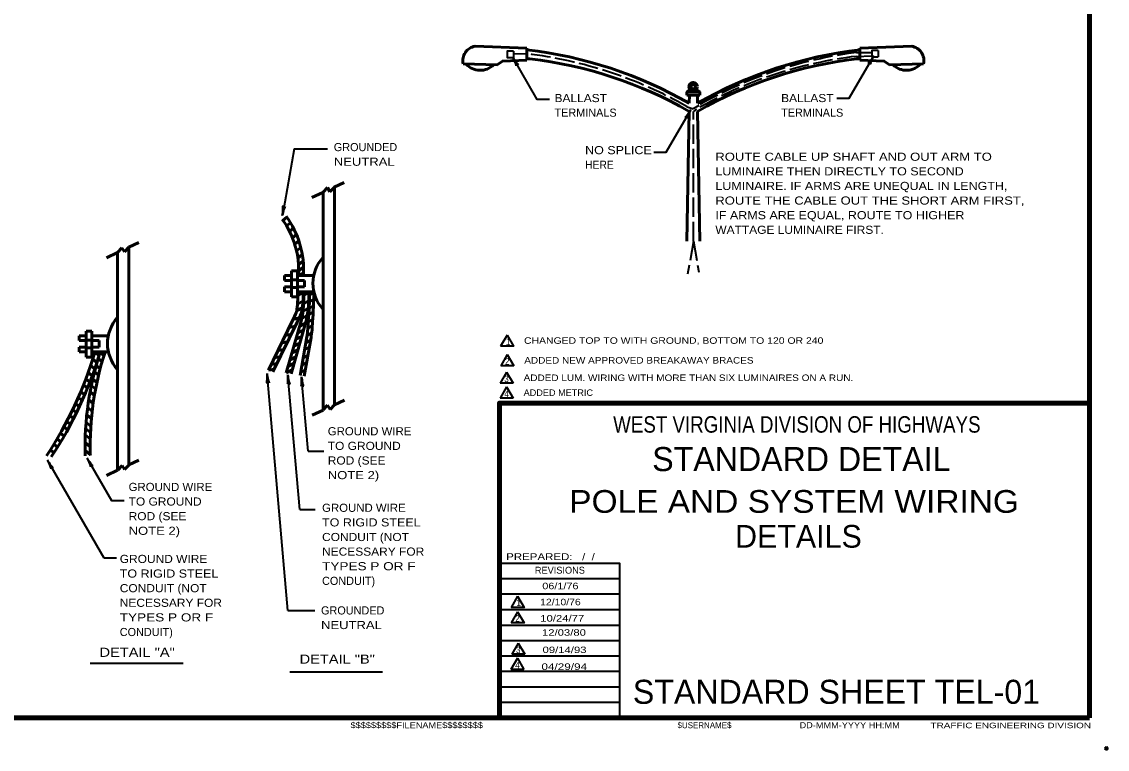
# Model space of a CAD drawing. Extents: x -217 to 639, y -295 to 249.
# Drawn here: x 237.5 to 638.6, y -295.3 to -26.5 of the extents above; entities that cross this region are included whole.
import ezdxf
from ezdxf.enums import TextEntityAlignment as Align

# ---------------------------------------------------------------- set-up
doc = ezdxf.new("R2010")
doc.units = 0
doc.header["$LTSCALE"] = 1.2
doc.header["$PDMODE"] = 32
doc.header["$PDSIZE"] = 0.6
doc.linetypes.add('LONG_DASHED', pattern=[7.5, 6, -1.5])
doc.layers.add('1', color=7, linetype='Continuous', lineweight=53)
doc.layers.add('61', color=7, linetype='Continuous', lineweight=35)

msp = doc.modelspace()

# ---------------------------------------------------------------- linework, layer by layer
at = {"layer": '1', "lineweight": 158}
for q in [(632.039, 242.399), (632.039, -167.401), (-159.561, -283.701)]:
    msp.add_line((632.039, -283.701), q, dxfattribs=at)
at = {"layer": '1', "lineweight": 13}
msp.add_line((632.039, -283.701), (632.039, 242.399), dxfattribs=at)
at = {"layer": '1'}
for p, q in [((424.221, -36.195), (405.032, -35.525)), ((547.171, -36.192), (566.359, -35.522)), ((424.221, -36.195), (424.221, -40.716)), ((547.171, -36.192), (547.171, -40.714)), ((413.197, -42.414), (400.605, -41.974)), ((425.309, -40.142), (424.221, -40.116)), ((546.082, -40.14), (547.171, -40.114)), ((558.195, -42.411), (570.787, -41.971)), ((483.289, -52.342), (484.754, -51.283)), ((488.089, -52.342), (486.541, -51.303)), ((483.289, -52.342), (488.089, -52.342)), ((483.289, -52.342), (483.289, -53.542)), ((483.289, -53.542), (488.089, -53.542)), ((484.221, -53.595), (484.17, -56.601)), ((487.171, -53.589), (487.221, -56.598)), ((488.089, -52.342), (488.089, -53.542)), ((484.121, -59.573), (483.321, -107.595)), ((487.271, -59.57), (488.071, -107.589)), ((348.857, -89.489), (350.494, -87.734)), ((350.494, -87.734), (351.42, -89.286)), ((351.42, -89.286), (353.057, -87.531)), ((352.992, -87.561), (356.709, -85.828)), ((353.057, -87.531), (353.057, -167.994)), ((344.745, -91.407), (348.79, -89.521)), ((348.857, -89.489), (348.857, -169.953)), ((335.495, -98.673), (334.058, -99.88)), ((336.827, -100.715), (335.382, -101.928)), ((337.981, -102.796), (336.521, -104.021)), ((277.062, -109.801), (280.778, -108.068)), ((337.526, -106.253), (337.485, -106.288)), ((339.027, -105.051), (337.543, -106.296)), ((338.405, -108.707), (339.923, -107.432)), ((339.843, -107.372), (339.89, -107.333)), ((268.815, -113.647), (272.86, -111.761)), ((272.927, -111.73), (274.564, -109.974)), ((272.927, -111.73), (272.927, -192.193)), ((274.564, -109.974), (275.49, -111.526)), ((275.49, -111.526), (277.127, -109.771)), ((277.127, -109.771), (277.127, -190.234)), ((340.626, -109.829), (339.062, -111.142)), ((341.185, -112.474), (339.557, -113.841)), ((341.502, -114.837), (339.801, -116.264)), ((334.67, -120.246), (334.67, -122.046)), ((334.67, -120.246), (337.17, -120.246)), ((337.21, -118.512), (339.37, -118.512)), ((339.37, -118.512), (339.37, -128.112)), ((339.387, -120.246), (345.47, -120.246)), ((341.645, -117.022), (339.862, -118.518)), ((341.647, -119.175), (340.371, -120.246)), ((334.67, -122.046), (337.21, -122.046)), ((337.21, -121.868), (339.37, -121.868)), ((339.367, -122.046), (342.01, -122.046)), ((342.01, -122.046), (342.01, -124.446)), ((334.67, -124.446), (334.67, -126.246)), ((334.67, -124.446), (337.21, -124.446)), ((334.67, -126.246), (337.17, -126.246)), ((337.21, -124.69), (339.37, -124.69)), ((337.21, -128.112), (339.37, -128.112)), ((339.346, -124.446), (342.01, -124.446)), ((339.387, -126.246), (345.47, -126.246)), ((341.461, -126.553), (339.63, -127.61)), ((339.659, -126.477), (339.659, -126.246)), ((343.526, -126.482), (341.764, -127.583)), ((345.519, -126.502), (343.879, -127.526)), ((341.201, -132.128), (339.114, -133.333)), ((341.47, -129.619), (339.418, -130.803)), ((343.39, -132.266), (341.441, -133.484)), ((343.56, -129.432), (341.707, -130.682)), ((345.403, -131.278), (343.7, -132.427)), ((345.512, -128.917), (343.847, -129.957)), ((339.974, -135.882), (337.809, -136.503)), ((343.043, -134.957), (340.998, -136.138)), ((345.049, -136.322), (343.4, -137.435)), ((345.23, -133.678), (343.594, -134.782)), ((337.607, -136.917), (328.665, -155.252)), ((339.31, -137.501), (330.367, -155.837)), ((340.9, -136.606), (335.277, -156.216)), ((338.613, -138.93), (336.35, -139.494)), ((342.659, -136.985), (337.036, -156.595)), ((342.408, -137.861), (340.236, -138.92)), ((344.903, -138.758), (343.252, -139.872)), ((258.74, -142.486), (258.74, -144.286)), ((258.74, -142.486), (261.239, -142.486)), ((258.74, -144.286), (261.28, -144.286)), ((261.28, -140.752), (263.44, -140.752)), ((261.28, -144.108), (263.44, -144.108)), ((263.436, -144.286), (266.08, -144.286)), ((263.44, -140.752), (263.44, -150.352)), ((263.456, -142.486), (269.54, -142.486)), ((266.08, -144.286), (266.08, -146.686)), ((337.161, -141.907), (334.944, -142.379)), ((341.005, -142.754), (338.833, -143.813)), ((341.683, -140.401), (339.51, -141.46)), ((342.864, -142.917), (340.357, -157.136)), ((344.416, -143.155), (341.902, -157.409)), ((344.273, -143.962), (342.465, -145.181)), ((344.679, -141.299), (342.935, -142.476)), ((258.74, -146.686), (258.74, -148.486)), ((258.74, -146.686), (261.28, -146.686)), ((261.28, -146.93), (263.44, -146.93)), ((263.416, -146.686), (266.08, -146.686)), ((334.417, -147.533), (332.243, -147.917)), ((335.778, -144.743), (333.603, -145.126)), ((339.581, -147.721), (337.409, -148.78)), ((340.283, -145.273), (338.111, -146.332)), ((343.82, -146.535), (342.02, -147.749)), ((258.74, -148.486), (261.239, -148.486)), ((261.28, -150.352), (263.44, -150.352)), ((263.456, -148.486), (269.54, -148.486)), ((263.789, -151.132), (265.29, -152.391)), ((264.562, -148.638), (266.083, -149.915)), ((265.715, -151.083), (265.706, -151.076)), ((265.751, -150.926), (267.205, -152.146)), ((266.478, -148.622), (267.906, -149.82)), ((333.151, -150.13), (330.933, -150.601)), ((338.86, -150.279), (336.688, -151.338)), ((342.807, -152.278), (340.999, -153.497)), ((343.277, -149.613), (341.469, -150.832)), ((262.13, -156.025), (263.593, -157.252)), ((263.023, -153.463), (264.466, -154.674)), ((264.389, -155.837), (265.893, -157.099)), ((264.997, -153.536), (266.477, -154.778)), ((330.913, -154.791), (328.738, -155.174)), ((331.88, -152.734), (329.706, -153.118)), ((337.449, -155.077), (335.277, -156.136)), ((338.215, -152.617), (336.043, -153.677)), ((342.323, -154.979), (340.515, -156.198)), ((261.252, -158.404), (262.697, -159.616)), ((263.744, -158.525), (265.277, -159.811)), ((259.369, -163.129), (260.78, -164.314)), ((260.384, -160.643), (261.813, -161.842)), ((262.771, -163.276), (264.361, -164.61)), ((263.242, -160.847), (264.802, -162.156)), ((257.434, -167.544), (258.816, -168.703)), ((258.44, -165.298), (259.837, -166.47)), ((262.282, -166.174), (263.908, -167.538)), ((348.924, -169.922), (350.561, -168.166)), ((350.561, -168.166), (351.487, -169.718)), ((351.487, -169.718), (353.124, -167.963)), ((353.059, -167.993), (356.776, -166.26)), ((255.31, -171.982), (256.664, -173.117)), ((256.391, -169.771), (257.758, -170.918)), ((261.554, -171.768), (263.257, -173.198)), ((261.884, -168.953), (263.548, -170.349)), ((344.812, -171.839), (348.857, -169.953)), ((253.15, -176.14), (254.478, -177.255)), ((254.209, -174.141), (255.55, -175.266)), ((261.302, -174.494), (263.046, -175.958)), ((251.849, -178.497), (253.164, -179.6)), ((261.026, -179.095), (262.846, -180.621)), ((261.14, -176.798), (262.922, -178.292)), ((249.446, -182.601), (250.738, -183.686)), ((250.656, -180.572), (251.96, -181.666)), ((260.95, -181.96), (262.821, -183.53)), ((248.153, -184.689), (249.435, -185.764)), ((260.948, -184.928), (262.889, -186.556)), ((262.866, -186.275), (262.902, -186.73)), ((277.129, -190.233), (280.846, -188.5)), ((268.882, -194.079), (272.927, -192.193)), ((272.994, -192.162), (274.631, -190.406)), ((274.631, -190.406), (275.557, -191.958)), ((275.557, -191.958), (277.194, -190.203))]:
    msp.add_line(p, q, dxfattribs=at)
at = {"layer": '1', "lineweight": 40}
for p, q in [((419.26, -37.319), (419.26, -39.719)), ((554.01, -37.078), (554.01, -39.478)), ((262.867, -263.504), (297.196, -263.504)), ((336.56, -266.732), (370.889, -266.732))]:
    msp.add_line(p, q, dxfattribs=at)
at = {"layer": '1', "linetype": 'LONG_DASHED', "lineweight": 40}
for p, q in [((424.044, -38.284), (419.26, -38.462)), ((486.823, -58.789), (485.721, -59.57))]:
    msp.add_line(p, q, dxfattribs=at)
at = {"layer": '1', "linetype": 'LONG_DASHED', "lineweight": 35}
for p, q in [((545.969, -37.846), (551.588, -37.823)), ((545.973, -39.246), (551.507, -39.108)), ((483.425, -57.903), (485.683, -58.586)), ((487.668, -57.379), (485.683, -58.586)), ((485.721, -107.595), (485.721, -59.57)), ((485.721, -107.595), (483.574, -119.768)), ((485.721, -107.595), (487.738, -119.034))]:
    msp.add_line(p, q, dxfattribs=at)
at = {"layer": '1', "lineweight": 35}
for p, q in [((338.16, -73.454), (333.83, -98.009)), ((338.16, -73.454), (350.487, -73.454)), ((416.84, -142.224), (414.44, -146.38)), ((416.899, -149.472), (414.499, -153.629)), ((416.899, -149.472), (419.299, -153.629)), ((416.656, -155.905), (414.256, -160.062)), ((419.299, -153.629), (414.499, -153.629)), ((416.656, -155.905), (419.056, -160.062)), ((335.852, -244.013), (328.191, -156.455)), ((340.245, -206.706), (335.891, -156.936)), ((343.351, -185.175), (340.943, -157.658)), ((419.056, -160.062), (414.256, -160.062)), ((416.656, -161.413), (414.256, -165.57)), ((416.656, -161.413), (419.056, -165.57)), ((419.056, -165.57), (414.256, -165.57)), ((267.984, -224.739), (247.038, -188.458)), ((343.351, -185.175), (349.104, -185.175)), ((340.245, -206.706), (345.986, -206.706)), ((272.542, -224.739), (267.984, -224.739)), ((458.539, -232.301), (414.039, -232.301)), ((458.539, -238.001), (414.039, -238.001)), ((420.72, -238.704), (418.32, -242.861)), ((335.852, -244.013), (345.781, -244.013)), ((458.539, -243.801), (414.039, -243.801)), ((420.738, -244.463), (418.338, -248.62)), ((458.539, -249.501), (414.039, -249.501)), ((458.539, -255.201), (414.039, -255.201)), ((420.999, -256.049), (418.599, -260.206)), ((420.999, -256.049), (423.399, -260.206)), ((423.399, -260.206), (418.599, -260.206)), ((458.539, -260.901), (414.039, -260.901)), ((420.685, -261.674), (418.285, -265.831)), ((420.685, -261.674), (423.085, -265.831)), ((458.539, -266.601), (414.039, -266.601)), ((423.085, -265.831), (418.285, -265.831)), ((458.539, -272.301), (414.039, -272.301)), ((458.539, -278.001), (414.039, -278.001))]:
    msp.add_line(p, q, dxfattribs=at)
at = {"layer": '1', "lineweight": 40}
for points in [[(419.26, -37.319), (416.86, -37.319), (416.86, -39.719), (419.26, -39.719)], [(554.01, -37.078), (551.61, -37.078), (551.61, -39.478), (554.01, -39.478)]]:
    msp.add_lwpolyline(points, dxfattribs=at)
at = {"layer": '1', "lineweight": 35}
for points in [[(432.565, -55.213), (428.007, -55.213), (418.933, -39.496)], [(538.715, -54.732), (543.272, -54.732), (552.346, -39.015)], [(471.107, -74.701), (475.665, -74.701), (484.739, -58.984)], [(416.84, -142.224), (419.24, -146.38), (414.44, -146.38)], [(275.346, -203.453), (270.788, -203.453), (261.714, -187.736)], [(458.539, -283.701), (458.539, -226.601), (414.039, -226.601)], [(420.72, -238.704), (423.12, -242.861), (418.32, -242.861)], [(420.738, -244.463), (423.138, -248.62), (418.338, -248.62)]]:
    msp.add_lwpolyline(points, dxfattribs=at)
at = {"layer": '1'}
for points in [[(424.221, -40.716), (415.226, -41.03), (413.197, -42.414)], [(547.171, -40.714), (556.166, -41.028), (558.195, -42.411)], [(483.53, -52.267), (487.766, -52.267), (483.61, -52.187), (487.605, -52.166), (483.771, -52.106), (487.505, -52.106), (483.891, -52.026), (487.404, -52.006), (484.012, -51.926), (487.244, -51.926), (484.132, -51.845), (487.123, -51.825), (484.273, -51.745), (486.983, -51.745), (487.846, -52.247), (486.481, -51.323), (487.846, -52.287), (486.461, -51.404), (486.702, -51.665), (486.34, -51.464), (486.642, -51.705), (486.26, -51.584), (486.381, -51.745), (486.2, -51.604), (486.1, -51.645), (485.999, -51.604), (486.361, -51.504), (485.979, -51.685), (486.722, -51.685), (485.939, -51.705), (486.762, -51.625), (486.441, -51.484), (486.862, -51.625), (486.802, -51.645), (484.212, -51.745), (483.49, -52.307), (484.694, -51.404), (484.514, -51.665), (484.775, -51.364), (484.614, -51.665)], [(484.614, -51.665), (484.855, -51.484), (484.775, -51.625), (484.895, -51.564), (484.955, -51.665), (485.096, -51.625), (485.176, -51.584), (485.156, -51.564), (485.055, -51.524), (484.955, -51.524), (484.935, -51.504), (484.935, -51.665), (484.734, -51.625), (484.594, -51.665), (484.453, -51.705), (484.534, -51.604), (484.453, -51.665)], [(484.453, -51.665), (484.775, -51.484), (484.895, -51.484), (484.975, -51.564), (485.096, -51.604), (485.116, -51.665), (484.915, -51.665), (484.775, -51.765), (485.658, -51.946), (486.12, -52.006), (485.156, -51.645)], [(337.21, -118.512), (337.21, -120.266), (337.21, -128.112)], [(261.28, -140.752), (261.28, -142.506), (261.28, -150.352)]]:
    msp.add_lwpolyline(points, dxfattribs=at)
at = {"layer": '1', "lineweight": 158}
msp.add_lwpolyline([(414.039, -283.701), (414.039, -167.401), (632.039, -167.401)], dxfattribs=at)
at = {"layer": '1', "lineweight": 90}
msp.add_circle((485.618, -50.46), 1.2, dxfattribs=at)
at = {"layer": '1'}
for centre, radius, start, end in [((405.916, -40.876), 5.424, 99.37905, 191.6795), ((565.475, -40.873), 5.424, 348.3205, 80.62095), ((405.617, -193.737), 158.041, 60.19516, 83.2397), ((565.775, -193.734), 158.041, 96.7603, 119.80484), ((406.954, -37.338), 7.08, 222.09121, 314.30098), ((407.058, -194.105), 155.041, 60.19516, 83.2397), ((564.333, -194.103), 155.041, 96.7603, 119.80484), ((564.437, -37.335), 7.08, 225.69902, 317.90879), ((307.876, -118.255), 31.987, 356.40839, 35.90092), ((307.876, -118.134), 33.787, 356.40839, 35.90092), ((359.509, -123.121), 14.361, 137.87912, 222.12088), ((285.937, -125.654), 53.728, 351.35006, 359.12221), ((316.025, -128.161), 25.487, 346.01908, 4.30944), ((302.95, -128.42), 38.823, 347.82744, 3.21036), ((302.95, -128.42), 40.623, 347.82752, 3.06797), ((220.22, -126.348), 123.662, 354.98062, 0.04745), ((219.978, -126.429), 125.462, 354.98066, 0.08358), ((283.579, -145.361), 14.361, 137.87912, 222.12088), ((259.319, -99.405), 86.811, 334.39874, 336.70651), ((361.358, -145.604), 23.49, 151.28461, 159.82064), ((301.58, -136.118), 41.841, 350.64855, 358.56325), ((303.131, -136.356), 41.841, 350.64855, 358.56325), ((124.237, -106.528), 146.507, 326.73645, 343.34848), ((124.448, -105.931), 148.307, 326.73645, 343.32557), ((373.827, -183.533), 112.888, 161.88261, 181.66408), ((373.907, -183.049), 111.088, 161.88261, 181.66408)]:
    msp.add_arc(centre, radius, start, end, dxfattribs=at)
at = {"layer": '1', "linetype": 'LONG_DASHED', "lineweight": 35}
for centre, radius, start, end in [((405.617, -193.737), 156.541, 60.19516, 83.2397), ((564.333, -194.103), 155.941, 96.76156, 119.80484), ((565.775, -193.734), 157.141, 97.24067, 119.80484)]:
    msp.add_arc(centre, radius, start, end, dxfattribs=at)
at = {"layer": '1', "lineweight": 40}
for centre, major_axis, ratio, start_param, end_param in [((419.385, -40.788), (-0.871, 1.931), 0.07063, 3.1407148, 5.41811), ((419.875, -40.464), (-1.234, 1.762), 0.122415, 0.8963533, 3.1415927), ((551.405, -39.983), (1.234, 1.762), 0.122415, 3.1415927, 5.386832), ((551.894, -40.306), (0.871, 1.931), 0.07063, 0.8650754, 3.1424706), ((483.797, -59.953), (1.234, 1.762), 0.122415, 3.1415927, 5.386832), ((484.287, -60.276), (0.871, 1.931), 0.07063, 0.8650754, 3.1424706), ((333.731, -96.662), (-0.188, -2.143), 0.122415, 0.8963533, 3.1415927), ((334.314, -96.729), (0.574, 2.039), 0.07063, 6.2823074, 8.5597026), ((328.056, -157.816), (-0.026, -2.118), 0.07063, 6.2823074, 8.5597026), ((328.636, -157.73), (-0.373, 2.118), 0.122415, 0.8963533, 3.1415927), ((335.755, -158.298), (-0.026, -2.118), 0.07063, 6.2823074, 8.5597026), ((336.335, -158.212), (-0.373, 2.118), 0.122415, 0.8963533, 3.1415927), ((340.807, -159.019), (-0.026, -2.118), 0.07063, 6.2823074, 8.5597026), ((341.388, -158.933), (-0.373, 2.118), 0.122415, 0.8963533, 3.1415927), ((247.49, -189.75), (-0.871, 1.931), 0.07063, 3.1407148, 5.41811), ((247.98, -189.426), (-1.234, 1.762), 0.122415, 0.8963533, 3.1415927), ((262.167, -189.028), (-0.871, 1.931), 0.07063, 3.1407148, 5.41811), ((262.656, -188.705), (-1.234, 1.762), 0.122415, 0.8963533, 3.1415927)]:
    msp.add_ellipse(centre, major_axis=major_axis, ratio=ratio, start_param=start_param, end_param=end_param, dxfattribs=at)
at = {"layer": '1'}
for p in [(484.453, -51.665), (638.339, -295.001)]:
    msp.add_point(p, dxfattribs=at)
at = {"layer": '61', "lineweight": 53}
for q in [(479.339, -283.701), (479.339, -283.701), (479.339, -283.701), (479.639, -283.701), (479.639, -283.701)]:
    msp.add_line((632.039, -283.701), q, dxfattribs=at)

# ---------------------------------------------------------------- texts
at = {"layer": '1'}
for s, height, width, p in [('BALLAST', 3, 1.1, (434.393, -56.158)), ('BALLAST', 3, 1.1, (518.12, -56.158)), ('NO SPLICE', 3, 1.15, (445.701, -75.406)), ('ROUTE CABLE UP SHAFT AND OUT ARM TO', 3, 1.2, (493.82, -77.838)), ('NEUTRAL  ', 3, 1.2, (352.844, -79.678)), ('HERE', 3, 0.95, (445.701, -80.806)), ('LUMINAIRE THEN DIRECTLY TO SECOND', 3, 1.15, (493.82, -83.238)), ('LUMINAIRE. IF ARMS ARE UNEQUAL IN LENGTH,', 3, 1.15, (493.82, -88.638)), ('ROUTE THE CABLE OUT THE SHORT ARM FIRST,', 3, 1.2, (493.82, -94.038)), ('IF ARMS ARE EQUAL, ROUTE TO HIGHER', 3, 1.15, (493.82, -99.438)), ('WATTAGE LUMINAIRE FIRST.', 3, 1.1, (493.82, -104.838)), ('CHANGED TOP TO WITH GROUND, BOTTOM TO 120 OR 240', 2.4, 1.2, (423.114, -145.472)), ('2', 2.4, 0.9, (416.095, -153.199)), ('ADDED NEW APPROVED BREAKAWAY BRACES', 2.4, 1.15, (423.221, -152.778)), ('3', 2.4, 0.9, (415.852, -159.631)), ('ADDED LUM. WIRING WITH MORE THAN SIX LUMINAIRES ON A RUN.', 2.4, 1.15, (422.978, -159.21)), ('4', 2.4, 0.95, (415.852, -165.139)), ('ADDED METRIC', 2.4, 1.05, (422.978, -164.718)), ('GROUND WIRE', 3, 1.05, (350.608, -179.283)), ('TO GROUND', 3, 1.1, (350.608, -184.683)), ('ROD (SEE', 3, 1.1, (350.608, -190.083)), ('NOTE 2)', 3, 1.2, (350.608, -195.483)), ('GROUND WIRE', 3, 1.05, (277.029, -199.855)), ('TO GROUND', 3, 1.1, (277.029, -205.255)), ('GROUND WIRE', 3, 1.05, (348.503, -207.557)), ('ROD (SEE', 3, 1.1, (277.029, -210.655)), ('TO RIGID STEEL', 3, 1.15, (348.503, -212.957)), ('NOTE 2)', 3, 1.2, (277.029, -216.055)), ('CONDUIT (NOT', 3, 1.1, (348.503, -218.357)), ('GROUND WIRE ', 3, 1.1, (273.751, -226.459)), ('NECESSARY FOR', 3, 1.1, (348.503, -223.757)), ('PREPARED:   /  /  ', 2.537, 1.25, (416.539, -225.401)), ('TYPES P OR F', 3, 1.25, (348.503, -229.157)), ('TO RIGID STEEL', 3, 1.15, (273.751, -231.859)), ('CONDUIT (NOT', 3, 1.1, (273.751, -237.259)), ('06/1/76', 2.4, 1.25, (429.87, -236.157)), ('NECESSARY FOR', 3, 1.1, (273.751, -242.659)), ('12/10/76', 2.4, 1.2, (429.075, -242.083)), ('TYPES P OR F', 3, 1.25, (273.751, -248.059)), ('NEUTRAL  ', 3, 1.2, (348.121, -250.882)), ('2', 2.4, 0.9, (419.908, -248.172)), ('10/24/77', 2.4, 1.3, (429.124, -248.115)), ('12/03/80', 2.4, 1.3, (429.762, -253.341)), ('3', 2.4, 0.9, (420.195, -259.775)), ('09/14/93', 2.4, 1.3, (429.977, -259.75)), ('4', 2.4, 0.95, (419.881, -265.4)), ('04/29/94', 2.4, 1.35, (429.565, -265.965)), ('$$$$$$$$$FILENAME$$$$$$$$', 2.2, 1.15, (359.039, -287.501)), ('DD-MMM-YYYY HH:MM', 2.2, 1.15, (524.939, -287.501)), ('TRAFFIC ENGINEERING DIVISION', 2.031, 1.35, (573.339, -287.501))]:
    msp.add_text(s, height=height, dxfattribs=dict(at, width=width)).set_placement(p)
for s, height, p in [('TERMINALS', 3, (434.393, -61.558)), ('TERMINALS', 3, (518.12, -61.558)), ('GROUNDED', 3, (352.844, -74.278)), ('1', 2.4, (416.355, -145.87)), ('REVISIONS', 2.537, (427.139, -230.401)), ('CONDUIT)', 3, (348.503, -234.557)), ('1', 2.4, (420.274, -242.324)), ('GROUNDED', 3, (348.121, -245.482)), ('CONDUIT)', 3, (273.751, -253.459)), ('STANDARD SHEET TEL-01', 8.881, (463.339, -278.501)), ('$USERNAME$', 2.2, (479.839, -287.501))]:
    msp.add_text(s, height=height, dxfattribs=at).set_placement(p)
for s, height, width, p in [('WEST VIRGINIA DIVISION OF HIGHWAYS', 6.089, 0.85, (523.939, -178.301)), ('POLE AND SYSTEM WIRING', 8.4, 1.1, (522.911, -207.921)), ('DETAIL "A"', 3.36, 1.2, (280.177, -261.141)), ('DETAIL "B"', 3.36, 1.2, (354.111, -263.648))]:
    msp.add_text(s, height=height, dxfattribs=dict(at, width=width)).set_placement(p, align=Align.CENTER)
for s, height, p in [('STANDARD DETAIL', 8.881, (525.589, -192.501)), ('DETAILS', 8.4, (524.518, -220.806))]:
    msp.add_text(s, height=height, dxfattribs=at).set_placement(p, align=Align.CENTER)

doc.saveas('drawing.dxf')
